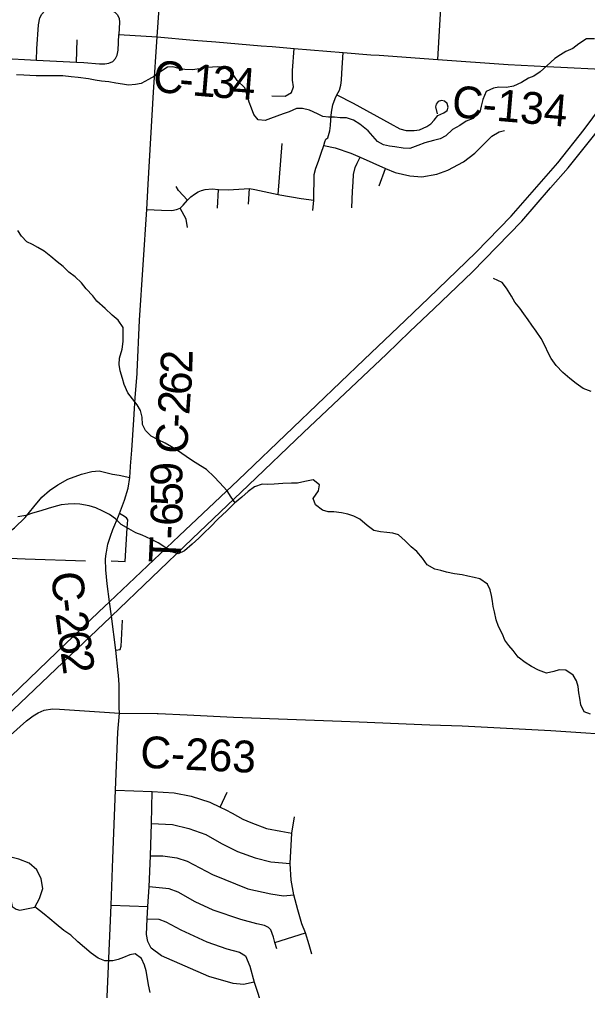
# Model space of a CAD drawing. Extents: x 114843 to 284848, y 317643 to 566895.
# Drawn here: x 185144 to 190513, y 345452 to 354619 of the extents above; entities that cross this region are included whole.
import ezdxf

# ---------------------------------------------------------------- set-up
doc = ezdxf.new("R2010")
doc.units = 0
for name, color, linetype in [('GM_X_City_Street', 7, 'Continuous'), ('GM_X_County_Road', 7, 'Continuous'), ('GM_X_County_Road_Text', 7, 'Continuous'), ('GM_X_Interstate_Route', 7, 'Continuous'), ('GM_X_Minor_Lake', 7, 'Continuous'), ('GM_X_Minor_River', 7, 'Continuous'), ('GM_X_Township_Road', 7, 'Continuous'), ('GM_X_Township_Road_Text', 7, 'Continuous')]:
    doc.layers.add(name, color=color, linetype=linetype)

msp = doc.modelspace()

# ---------------------------------------------------------------- linework, layer by layer
at = {"layer": 'GM_X_City_Street'}
for p, q in [((185684.6, 354216.2), (185690.9, 354427.4)), ((186084.9, 354478.3), (186445.3, 354455.2)), ((187589.1, 352967.6), (187625.9, 353447)), ((188543.3, 353048), (188604.5, 353212.6)), ((187014.4, 352836.4), (187024.4, 353014.5)), ((187310, 352875.8), (187317.8, 353024.6)), ((187042, 347184.6), (187106.8, 347325.2)), ((186009.6, 346258.3), (186358.7, 346245.2)), ((187556.9, 345905.7), (187846.2, 345996.4))]:
    msp.add_line(p, q, dxfattribs=at)
for points in [[(189096.8, 354241.4), (189134.3, 354893.5), (189134, 354939), (189124.5, 355023.3), (189115.2, 355085.4), (189114.8, 355140.9), (189117.7, 355196.4), (189149.3, 355586.2), (189179.9, 355961.6), (189186.1, 356024.9), (189193.5, 356068.2), (189209.9, 356112.7), (189220.8, 356136.1), (189280, 356239.7), (189300.6, 356303.1), (189311.1, 356385.3), (189316, 356473.4)], [(184656.5, 354762.2), (184656.3, 354475.3), (184656.3, 354469.1), (184659.8, 354343), (184668.3, 354323.2), (184678.9, 354301.4), (184693.4, 354281.8), (184749.8, 354267.3), (184962, 354253.1), (185306.3, 354235.5), (185684.6, 354216.2), (185752.7, 354212.7), (185899.4, 354200.9), (185949.8, 354199.6), (185990.5, 354205.9), (186026, 354222.7), (186051, 354249.8), (186068.1, 354280.3), (186077.3, 354329.8), (186084.9, 354478.3)], [(185306.3, 354235.5), (185307.5, 354340.7), (185325.1, 354569.6), (185337.4, 354634), (185354.4, 354668.6), (185379.6, 354697.3), (185422.8, 354724.5), (185484.5, 354734.2), (185576.3, 354742.8), (185913, 354717.6), (185959.9, 354716.2), (186007.3, 354707), (186046.1, 354689), (186072.3, 354662.3), (186085.5, 354629.4), (186090.2, 354593), (186084.9, 354478.3)], [(187530.4, 353897.9), (187656.7, 353894.5), (187714.3, 353929.2), (187733.2, 353982.8), (187724.2, 354044.9), (187725.6, 354136.9), (187739.1, 354344.7)], [(187917.5, 352815.7), (187925.7, 352913.5), (187928, 353156.8), (187945.4, 353215.8), (187970.4, 353281.4), (187994.5, 353356.8), (188020.4, 353429.1), (188029.8, 353464), (188038.3, 353490.1), (188059.8, 353500.1), (188077.1, 353567.9), (188084.4, 353616.5), (188085.3, 353671.4), (188092.5, 353743), (188106, 353813.4), (188127.3, 353873.2)], [(188020.4, 353429.1), (188128.8, 353407.5), (188275.4, 353356), (188362.5, 353318.1), (188604.5, 353212.6), (188693.3, 353175.2), (188831.9, 353141.7), (188946.2, 353134.1), (189088.6, 353158.9), (189192.7, 353197.5), (189338.9, 353274.4), (189448.9, 353357.3), (189538.8, 353448), (189606.8, 353518.6), (189676.8, 353557.1), (189726.9, 353569.4)], [(188283.7, 352841.9), (188291.2, 352998.4), (188298, 353083.5), (188301.2, 353155.6), (188317.6, 353222.9), (188335.8, 353263.1), (188362.5, 353318.1)], [(186733.4, 352911.7), (186645.9, 353003.1), (186625.7, 353043.7)], [(186346.8, 352826.4), (186487.5, 352819.6), (186585.6, 352816.9), (186628.1, 352825.9), (186663.6, 352839.1), (186690.3, 352866.2), (186733.4, 352911.7), (186764.4, 352944.9), (186799, 352971.2), (186831.8, 352991.4), (186864.7, 353004.6), (186898.5, 353012.7), (186966.6, 353018.9), (187024.4, 353014.5), (187118.1, 353011.7), (187317.8, 353024.6), (187370, 353014.3), (187589.1, 352967.6), (187605.7, 352964.1), (187805, 352927.3), (187925.7, 352913.5)], [(186733.5, 352656.5), (186720.8, 352734.5), (186663.6, 352839.1)], [(184859.5, 349665.4), (184880.1, 349612.7), (184897.1, 349579.2), (184913, 349559.3), (184937.3, 349544.8), (184971, 349535.6), (185197.9, 349527.8), (185769.5, 349508.8)], [(183357.3, 345349.2), (183381, 345685.8), (183381.3, 346045.3), (183386.5, 346123.7), (183420.8, 346199.3), (184129.2, 346991), (184784.2, 347618.1), (185210.8, 347999.8), (185274.8, 348047), (185321.4, 348074.7), (185377.9, 348098.5), (185455.8, 348112.7), (185522.2, 348109.3), (186088.3, 348070.5)], [(186053, 347342.9), (186397.5, 347331.9), (186605.9, 347318.6), (186767, 347286.4), (186942.3, 347231.3), (187042, 347184.6), (187094.1, 347158.3), (187152.9, 347125.3), (187254.9, 347069.7), (187332.2, 347038.3), (187479.4, 346983), (187614.5, 346955.8), (187718.6, 346937)], [(187363.5, 345530.9), (187261.6, 345509.1), (187162.3, 345517.4), (186933.5, 345584.9), (186487.5, 345780), (186387.8, 345851.4), (186357.3, 345914.4), (186344.8, 345980.4), (186352.7, 346127.7), (186358.7, 346245.2), (186370.4, 346430.1), (186381.5, 346723), (186391.2, 347029.3), (186397.5, 347331.9)], [(187907.7, 345795.5), (187881.5, 345882.5), (187846.2, 345996.4), (187814, 346083.4), (187774, 346215.3), (187738.4, 346354.8), (187713.4, 346494.4), (187702.1, 346652.3), (187718.6, 346937), (187742.9, 347092.6)], [(186391.2, 347029.3), (186589.7, 347019.1), (186746.2, 346981.1), (186905.8, 346925.2), (187054.4, 346839.8), (187204.4, 346765), (187373.1, 346706.1), (187520.6, 346668.1), (187702.1, 346652.3)], [(186381.5, 346723), (186498.7, 346723.8), (186631, 346703.8), (186730.4, 346674.4), (186968.7, 346546.9), (187303.9, 346411.8), (187519, 346363.8), (187637.9, 346345.1), (187738.4, 346354.8)], [(187576.8, 345847.2), (187556.9, 345905.7), (187544.5, 345955.2), (187518.5, 346024.1), (187498.8, 346046.5), (187459.6, 346065.8), (187387.4, 346083.3), (187236.9, 346122.8), (186974.8, 346212.6), (186805.2, 346290.3), (186645.3, 346382.3), (186558, 346411.7), (186464.8, 346423), (186370.4, 346430.1)], [(186352.7, 346127.7), (186460.9, 346125.5), (186527.2, 346101.9), (186668.9, 346024.8), (186916.1, 345912.4), (187102.9, 345847.6), (187223.3, 345815.4), (187280.6, 345779.7), (187320.4, 345680.9), (187363.5, 345530.9), (187442.7, 345281.3), (187496.7, 345116.9)]]:
    msp.add_lwpolyline(points, dxfattribs=at)
at = {"layer": 'GM_X_County_Road'}
for p, q in [((187429.1, 354371.2), (187532.4, 354362.3)), ((186190.3, 350345.5), (186194.4, 350397.2))]:
    msp.add_line(p, q, dxfattribs=at)
for points in [[(186256.7, 351272.9), (186258.1, 351288.3), (186278.9, 351779.8), (186346.8, 352826.4), (186359.9, 353064.4), (186410.9, 353932.9), (186445.3, 354455.2), (186507.1, 355361.3)], [(186445.3, 354455.2), (186790.2, 354423.5), (187000.1, 354407.8), (187429.1, 354371.2)], [(187532.4, 354362.3), (187739.1, 354344.7), (188203.3, 354305.8), (188463.9, 354286.5)], [(188463.9, 354286.5), (188542, 354280.7), (189096.8, 354241.4), (189761.4, 354194.4), (190132.1, 354175.8), (190770.8, 354143.6)], [(186194.4, 350397.2), (186194.8, 350402.4), (186206.1, 350553.5), (186224, 350841), (186237.2, 351051.2), (186256.7, 351272.9)], [(184859.5, 349665.4), (184919.8, 349700.1), (185009.2, 349754), (185097, 349818.9), (185199.7, 349916.4), (185279, 350017.1), (185355.1, 350109.4), (185428, 350171.6), (185507.7, 350225.6), (185602.4, 350279.6), (185732.2, 350327.3), (185827.1, 350353), (185898.8, 350356.8), (185960.6, 350343.9), (186024.1, 350326), (186085.9, 350316.5), (186186.1, 350293.8)], [(186078.9, 349931.6), (186089.1, 349956.4), (186135.7, 350082.4), (186170.2, 350193.6), (186186.1, 350293.8), (186190.3, 350345.5)], [(185964.4, 349578), (185965.6, 349589), (185980.7, 349664.6), (186004, 349741.6), (186025.7, 349803), (186078.9, 349931.6)], [(186078.5, 348452.2), (186056.5, 348666), (186012.8, 348985), (185994.9, 349120.9), (185972.1, 349293), (185960.7, 349424), (185958.4, 349522.8), (185964.4, 349578)], [(186088, 348124.5), (186087.5, 348216.5), (186086.9, 348277.8), (186085.3, 348337), (186080.7, 348430.9), (186078.5, 348452.2)], [(185952.6, 344888.8), (186009.6, 346258.3), (186025.5, 346698.5), (186053, 347342.9), (186072.5, 347890), (186088.3, 348070.5), (186088, 348124.5)], [(186088.3, 348070.5), (186444.7, 348066.4), (186455.2, 348066)], [(186455.2, 348066), (186728.8, 348054.2), (187166.6, 348033.8), (187591.7, 348017.5), (188187.4, 347995.2)], [(188187.4, 347995.2), (188354.7, 347988.9), (189023.3, 347960.2), (189329, 347950.5), (190166.3, 347908.4), (190917.1, 347857.4), (191544.9, 347823.3)]]:
    msp.add_lwpolyline(points, dxfattribs=at)
at = {"layer": 'GM_X_Interstate_Route'}
for points in [[(190054.5, 353063.9), (190230.9, 353266), (190481.5, 353580.8), (190725.6, 353912.1), (190880.7, 354138), (191145.5, 354544.6), (191359.2, 354912.4)], [(190163.8, 353028.4), (190329.8, 353218.7), (190580.4, 353533.4), (190824.5, 353864.7), (191006.6, 354131.3), (191244.3, 354497.3), (191441.3, 354821.4), (191472.4, 354877.2)], [(188722.5, 351715.3), (189010, 351988), (189457.7, 352420.3), (189791.7, 352762.6), (190054.5, 353063.9)], [(188833.9, 351672.2), (189062.8, 351890.8), (189422.7, 352234.6), (189890.6, 352715.3), (190163.8, 353028.4)], [(185895.9, 349026.3), (185994.9, 349120.9), (186653.2, 349744), (187209.8, 350270), (187729.5, 350766), (188400.5, 351410), (188722.5, 351715.3)], [(186005.2, 348977.7), (186012.8, 348985), (186777.7, 349715.4), (187308.6, 350222.7), (187828.4, 350718.6), (188612.6, 351460.8), (188833.9, 351672.2)], [(183841.4, 347059.4), (183867.5, 347085.5), (184162.5, 347368.7), (184710.9, 347889.9), (185412.6, 348564.3), (185895.9, 349026.3)], [(183940.3, 347012), (183966.3, 347038.2), (184261.4, 347321.4), (184809.8, 347842.6), (185556.2, 348551.9), (186005.2, 348977.7)]]:
    msp.add_lwpolyline(points, dxfattribs=at)
at = {"layer": 'GM_X_Minor_Lake'}
for points in [[(185288.9, 346238.4), (185333, 346322.5), (185365.2, 346414.6), (185349.3, 346506.8), (185307.4, 346591.1), (185237.5, 346655.3), (185139.5, 346693.5), (184999.4, 346727.8), (184845.3, 346736), (184727.3, 346732.2), (184663.2, 346742.3), (184615.2, 346744.3), (184599.1, 346724.3), (184601.1, 346700.3), (184735.1, 346642), (184869.2, 346633.8), (185015.2, 346605.5), (185053.2, 346565.4), (185067, 346443.1), (185066.9, 346348.9), (185064.8, 346292.8), (185074.7, 346246.7), (185112.7, 346220.6), (185148.7, 346212.5)], [(185148.7, 346212.5), (185288.9, 346238.4)]]:
    msp.add_lwpolyline(points, dxfattribs=at)
at = {"layer": 'GM_X_Minor_River'}
for points in [[(190576.9, 354435.2), (190500.9, 354437.3), (190430.7, 354387.3), (190372.6, 354345.3), (190306.5, 354317.3), (190256.5, 354285.3), (190204.4, 354249.3), (190128.2, 354181.3), (190064.1, 354125.3), (190004, 354083.3), (189953.9, 354063.3), (189889.8, 354025.3), (189811.7, 353989.4), (189747.7, 353977.5), (189673.6, 353979.6), (189623.6, 353971.6), (189555.5, 353937.7), (189523.3, 353863.6), (189507.2, 353799.4), (189493.1, 353743.4), (189433, 353683.3), (189366.9, 353657.4), (189304.8, 353617.4), (189236.7, 353579.4), (189174.6, 353521.4), (189120.5, 353493.4), (189056.4, 353477.5)], [(189056.4, 353477.5), (188974.3, 353455.5), (188910.3, 353429.6), (188834.2, 353401.6), (188770.1, 353403.7), (188692.1, 353415.9), (188640.1, 353422), (188584.1, 353436.1), (188526.1, 353466.2), (188484.1, 353516.4), (188438.2, 353568.6), (188362.2, 353630.8), (188300.2, 353669), (188234.2, 353691.1), (188176.2, 353691.2), (188120.1, 353695.3), (188066.1, 353697.4), (188012.1, 353701.5), (187960.1, 353729.6), (187886.1, 353761.8), (187818.1, 353779.9), (187762, 353778), (187691.9, 353748), (187635.9, 353728), (187575.8, 353706.1), (187517.7, 353684.1), (187467.7, 353666.2), (187399.6, 353670.3), (187357.7, 353720.4), (187335.8, 353782.6), (187315.8, 353836.7), (187297.9, 353892.9), (187274, 353973.1), (187202.1, 354043.3), (187158.1, 354107.5), (187078.2, 354169.7), (187018.1, 354171.8), (186968.1, 354167.9), (186918.1, 354164), (186850, 354152), (186777.9, 354144.1), (186707.9, 354146.2), (186653.9, 354156.3), (186593.8, 354170.4), (186543.8, 354168.5), (186471.7, 354120.5), (186421.6, 354084.5), (186363.5, 354052.5), (186293.4, 354014.6), (186241.4, 354004.6), (186173.3, 353998.7), (186117.3, 354006.8), (186055.3, 354016.9), (185989.2, 354029), (185919.2, 354037.1), (185861.2, 354047.2), (185797.1, 354057.3), (185699.1, 354069.5), (185633.1, 354077.6), (185553, 354085.7), (185487, 354087.8), (185434.9, 354085.9), (185364.9, 354086), (185302.9, 354088.1), (185242.8, 354090.2), (185184.8, 354092.3), (185116.7, 354096.4)], [(187182.5, 350056.7), (187146, 350109.5), (187108.1, 350169.7), (187036.2, 350248), (186984.2, 350300.1), (186910.3, 350370.4), (186854.3, 350406.6), (186780.3, 350452.7), (186718.3, 350492.9), (186638.4, 350549.1), (186580.4, 350583.3), (186522.4, 350619.5), (186456.4, 350651.6), (186388.4, 350685.8), (186336.5, 350738), (186308.5, 350794.1), (186302.6, 350866.3), (186286.7, 350928.4), (186256.8, 350982.6), (186168.9, 351094.9), (186135, 351173.1), (186117.1, 351231.3), (186095.1, 351303.4), (186087.2, 351361.6), (186091.3, 351421.7), (186113.5, 351507.8), (186123.6, 351579.9), (186123.8, 351710.2), (186075.9, 351780.4), (186019.9, 351828.6), (185953.9, 351890.8), (185874, 351961.1), (185838.1, 352011.2), (185776.1, 352077.4), (185730.2, 352133.6), (185672.2, 352189.8), (185612.2, 352234), (185556.3, 352288.2), (185500.3, 352332.3), (185442.4, 352380.5), (185376.4, 352432.7), (185318.4, 352466.8), (185266.4, 352495), (185214.4, 352521.1), (185164.5, 352573.3), (185128.5, 352625.4)], [(190545.8, 351106.6), (190471.8, 351134.7), (190403.8, 351182.9), (190343.9, 351231.1), (190277.9, 351287.3), (190216, 351351.6), (190170, 351419.7), (190138.1, 351477.9), (190116.2, 351530.1), (190074.3, 351606.3), (190028.3, 351676.5), (189984.4, 351734.6), (189950.5, 351784.8), (189910.5, 351841), (189872.6, 351895.1), (189826.6, 351951.3), (189794.7, 352007.5), (189746.8, 352081.7), (189704.8, 352135.9), (189624.8, 352174)], [(190539.2, 348062.5), (190479.2, 348082.6), (190449.3, 348148.8), (190439.3, 348213), (190431.4, 348263.1), (190423.5, 348321.2), (190407.6, 348375.3), (190375.6, 348429.5), (190305.7, 348477.7), (190245.6, 348479.8), (190193.6, 348463.8), (190123.5, 348447.9), (190049.5, 348478), (189981.5, 348512.2), (189921.5, 348550.4), (189857.6, 348600.6), (189809.6, 348660.8), (189767.7, 348710.9), (189731.7, 348761.1), (189707.8, 348815.2), (189671.9, 348889.4), (189649.9, 348951.6), (189634.1, 349027.8), (189622.1, 349077.9), (189614.2, 349128), (189604.3, 349180.1), (189592.3, 349236.2), (189568.4, 349288.4), (189494.4, 349338.6), (189440.4, 349350.7), (189382.4, 349364.8), (189326.4, 349374.9), (189256.3, 349387), (189180.3, 349401.1), (189126.3, 349417.3), (189070.3, 349431.4), (188998.3, 349469.6), (188952.4, 349533.7), (188898.4, 349596), (188846.5, 349640.1), (188790.5, 349696.3), (188724.5, 349752.5), (188672.5, 349770.6), (188614.5, 349776.7), (188554.5, 349780.8), (188494.5, 349794.9), (188430.5, 349841.1), (188360.5, 349901.3), (188304.5, 349931.5), (188248.5, 349947.6), (188188.5, 349961.7), (188114.5, 349969.8), (188060.4, 349971.9), (188006.4, 349988), (187942.5, 350036.2), (187920.5, 350098.4), (187970.7, 350170.5), (187980.8, 350224.6), (187920.8, 350274.7), (187840.7, 350258.8), (187772.7, 350242.9), (187714.6, 350241), (187634.6, 350239.1), (187552.5, 350231.2), (187492.5, 350229.3), (187436.4, 350231.4), (187366.3, 350207.4), (187306.2, 350163.4), (187246.1, 350109.4), (187176, 350051.4), (187099.8, 349977.3), (187021.6, 349905.3), (186947.5, 349827.2), (186891.4, 349777.2), (186839.2, 349723.2), (186777.1, 349667.2), (186703, 349603.2), (186644.9, 349573.2), (186574.9, 349595.3), (186508.9, 349643.5), (186454.9, 349677.7), (186386.9, 349711.8), (186302.9, 349752), (186244.9, 349774.2), (186178.9, 349810.3), (186104.9, 349852.5), (186053, 349904.7), (185995, 349946.9), (185931, 349979), (185865, 350009.2), (185803, 350027.3), (185715, 350043.4), (185662.9, 350047.5), (185604.9, 350043.6)], [(185604.9, 350043.6), (185538.8, 350035.7), (185470.8, 350017.7), (185416.7, 350001.8), (185346.6, 349981.8), (185268.5, 349957.9), (185204.5, 349938), (185130.4, 349924)], [(186380.4, 345433.2), (186364.5, 345505.4), (186350.6, 345585.5), (186342.7, 345639.7), (186326.7, 345691.8), (186298.8, 345756), (186236.8, 345798.2), (186186.8, 345788.2), (186128.7, 345764.2), (186076.6, 345744.3), (186026.6, 345732.3), (185952.5, 345732.4), (185888.5, 345758.6), (185822.6, 345804.7), (185758.6, 345859), (185694.6, 345911.1), (185628.7, 345975.4), (185562.7, 346019.6), (185490.8, 346077.8), (185430.8, 346128), (185378.8, 346172.1), (185290.6, 346241.6)]]:
    msp.add_lwpolyline(points, dxfattribs=at)
at = {"layer": 'GM_X_Township_Road'}
msp.add_line((186010.5, 349509.4), (186142.5, 349503.5), dxfattribs=at)
for points in [[(188127.3, 353873.2), (188144.6, 353906.4), (188168.9, 353953), (188180, 353997.8), (188187.3, 354046.4), (188192, 354111.6), (188203.3, 354305.8)], [(188144.6, 353906.4), (188297, 353829.2), (188647.4, 353635.9), (188737.5, 353586.4), (188799.4, 353569.9), (188874.1, 353569.6), (188923.1, 353578.4), (188992.4, 353607.7), (189032.9, 353635.1), (189063.2, 353669.3), (189096.8, 353713.6), (189155.9, 353736.1), (189186.2, 353760), (189195.3, 353789.8), (189186.6, 353825.3), (189160.2, 353846.3), (189132.2, 353853.7), (189100.9, 353845), (189081.6, 353819.5), (189076.7, 353795.7), (189089.9, 353729.6)], [(186142.5, 349503.5), (186162.9, 349821.6), (186167.1, 349894.3), (186154.7, 349915.6), (186120.8, 349936.8), (186089.1, 349956.4)], [(186056.5, 348666), (186097.3, 348671.5), (186104, 348703.6), (186109.6, 348761), (186117.8, 348949.4)]]:
    msp.add_lwpolyline(points, dxfattribs=at)

# ---------------------------------------------------------------- texts
at = {"layer": 'GM_X_County_Road_Text'}
for s, height, rotation, p in [('C', 300, 353.9357, (186396.2, 353940.6)), ('1', 300, 355.13756, (186770.8, 353902.6)), ('3', 300, 355.57558, (186957.4, 353886.7)), ('4', 300, 355.69118, (187142.3, 353872.4)), ('-', 300, 354.72339, (186645.7, 353914.1)), ('C-134', 300.02, 355.11328, (189222.9, 353698.9)), ('2', 300, 89.66517, (186778.9, 351275.7)), ('6', 300, 84.87271, (186761.1, 351064.2)), ('2', 300, 86.11043, (186748.7, 350881.6)), ('-', 300, 86.78062, (186741.8, 350759.5)), ('C', 300, 86.94495, (186728.7, 350513.6)), ('C', 300, 275.11337, (185444.8, 349395.7)), ('-', 300, 277.13353, (185468, 349138.8)), ('2', 300, 277.55918, (185483.6, 349014.1)), ('6', 300, 277.73058, (185508.1, 348829.9)), ('2', 300, 277.77228, (185532.9, 348646.5)), ('C-263', 300.02, 357.3855, (186281.2, 347556.6))]:
    msp.add_text(s, height=height, rotation=rotation, dxfattribs=at).set_placement(p)
at = {"layer": 'GM_X_Township_Road_Text'}
for s, rotation, p in [('9', 91.66409, (186687, 350223.3)), ('5', 89.74006, (186686.3, 350027.5)), ('6', 88.41668, (186681, 349835.2)), ('-', 87.61193, (186675.7, 349707.5)), ('T', 87.36006, (186665.4, 349481.9))]:
    msp.add_text(s, height=300, rotation=rotation, dxfattribs=at).set_placement(p)

doc.saveas('drawing.dxf')
